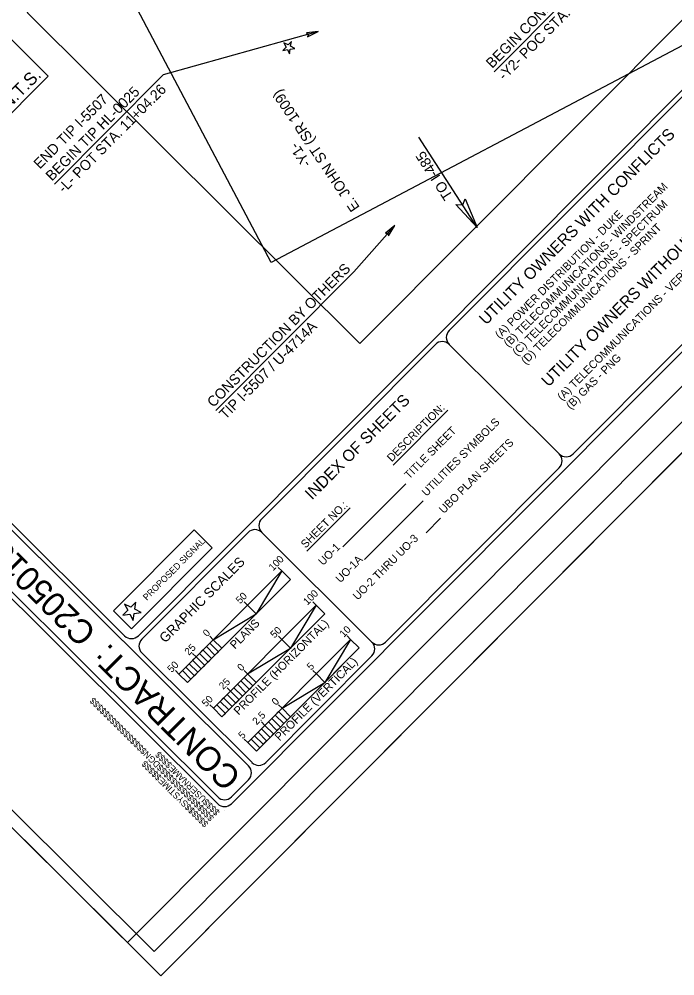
# Model space of a CAD drawing. Extents: x 1484850 to 1495577, y 495475 to 506245.
# Drawn here: x 1486921 to 1488945, y 495475 to 498431 of the extents above; entities that cross this region are included whole.
import ezdxf

# ---------------------------------------------------------------- set-up
doc = ezdxf.new("R2010")
doc.units = 0
for name, color, linetype in [('Cell Prop Down Guy _B', 7, 'Continuous'), ('Exist Conduit _B', 7, 'Continuous'), ('Exist Utilities Power UG Cable SUE LOS C', 7, 'Continuous'), ('Exist Utilities Sanitary Sewer Manhole CELL', 7, 'Continuous'), ('Exist Utilities Telephone Pedestal CELL', 7, 'Continuous'), ('Exist Utilities Telephone UG Cable SUE LOS C', 7, 'Continuous'), ('Exist Utilities Telephone UG FO SUE LOS C', 7, 'Continuous'), ('Exist Utilities TV UG Cable SUE LOS C', 7, 'Continuous'), ('Exist Utilities Water Meter CELL', 7, 'Continuous'), ('Exist Utilities Water UG Line SUE LOS B', 7, 'Continuous'), ('Exist Utilities Water Valve CELL', 7, 'Continuous'), ('P Pole (Pow Co) CELL', 7, 'Continuous'), ('Prop Guy Wire', 7, 'Continuous'), ('Prop UG Pow Cables', 7, 'Continuous')]:
    doc.layers.add(name, color=color, linetype=linetype)

msp = doc.modelspace()

# ---------------------------------------------------------------- linework, layer by layer
at = {"layer": 'Cell Prop Down Guy _B'}
for p, q in [((1487357.7, 495475.3), (1490922.5, 499055)), ((1485019.4, 497803.9), (1487357.7, 495475.3))]:
    msp.add_line(p, q, dxfattribs=at)
msp.add_lwpolyline([(1485019.4, 497803.9), (1488584.2, 501383.6), (1490922.5, 499055), (1487357.7, 495475.3)], close=True, dxfattribs=at)
at = {"layer": 'Exist Conduit _B'}
for p, q in [((1487731.5, 496726.7), (1487720.9, 496737.3)), ((1487625.7, 496620.5), (1487615.1, 496631)), ((1487466.9, 496461), (1487456.3, 496471.6)), ((1487414, 496407.9), (1487403.4, 496418.4)), ((1487555.1, 495985.8), (1487555.1, 495985.8))]:
    msp.add_line(p, q, dxfattribs=at)
at = {"layer": 'Exist Utilities Power UG Cable SUE LOS C'}
for p, q in [((1488075.3, 497053.3), (1488244.1, 497222.9)), ((1487920.3, 496801.3), (1488114.2, 496996)), ((1487987.3, 496761.4), (1488167.8, 496942.6)), ((1487809.4, 496787.4), (1487943, 496921.1)), ((1488177.1, 496844.7), (1488221.4, 496889.2))]:
    msp.add_line(p, q, dxfattribs=at)
at = {"layer": 'Exist Utilities Sanitary Sewer Manhole CELL'}
for points in [[(1487811.4, 498377.2), (1487844.4, 498392.9), (1487807.8, 498389.3), (1487813.9, 498384.4)], [(1488297.6, 497876.3), (1488335.3, 497788.1), (1488269.5, 497858.8), (1488290.2, 497857.8)], [(1488061.2, 497762.3), (1488080.4, 497793.4), (1488051.6, 497770.5), (1488059.5, 497769.8)]]:
    msp.add_lwpolyline(points, close=True, dxfattribs=at)
at = {"layer": 'Exist Utilities Telephone Pedestal CELL'}
for points in [[(1487744.7, 498345.3), (1487734.4, 498335), (1487748.8, 498337.3), (1487755.4, 498324.4), (1487757.6, 498338.7), (1487772, 498341), (1487759, 498347.6), (1487761.3, 498361.9), (1487751, 498351.6), (1487738, 498358.2), (1487744.7, 498345.3)], [(1487256.1, 496604.9), (1487240.7, 496589.5), (1487262.2, 496592.9), (1487272.2, 496573.5), (1487275.5, 496595.1), (1487297, 496598.5), (1487277.6, 496608.4), (1487281, 496629.9), (1487265.6, 496614.4), (1487246.1, 496624.3), (1487256.1, 496604.9)]]:
    msp.add_lwpolyline(points, dxfattribs=at)
at = {"layer": 'Exist Utilities Telephone UG Cable SUE LOS C'}
msp.add_lwpolyline([(1486945.7, 498451.8), (1488980.9, 500495.4), (1490008.1, 499472.4), (1487973, 497428.8)], close=True, dxfattribs=at)
msp.add_lwpolyline([(1486945.7, 498451.8), (1488980.9, 500495.4), (1490008.1, 499472.4), (1487973, 497428.8)], close=True, dxfattribs=at)
at = {"layer": 'Exist Utilities Telephone UG FO SUE LOS C'}
msp.add_lwpolyline([(1487208.7, 498608.1), (1488222.1, 499143.2), (1488965.4, 498493.7), (1489025.4, 498380), (1487698.9, 497679.6)], close=True, dxfattribs=at)
at = {"layer": 'Exist Utilities TV UG Cable SUE LOS C'}
msp.add_lwpolyline([(1487211.7, 496602.9), (1487460.9, 496853.2), (1487516.6, 496797.6), (1487267.4, 496547.4)], close=True, dxfattribs=at)
at = {"layer": 'Exist Utilities Water Meter CELL'}
msp.add_line((1488335.3, 497788.1), (1488154.6, 498067.2), dxfattribs=at)
msp.add_lwpolyline([(1486217.1, 497689.6), (1486895.2, 498370.5), (1487010.5, 498255.7), (1486332.4, 497574.8)], close=True, dxfattribs=at)
at = {"layer": 'Exist Utilities Water UG Line SUE LOS B'}
for p, q in [((1488751.5, 498634.5), (1488387.4, 498268.8)), ((1487844.4, 498392.9), (1487365, 498259)), ((1487365, 498259), (1487029.3, 497921.9)), ((1487954.1, 497650.7), (1488080.4, 497793.4)), ((1487954.1, 497650.7), (1487527.6, 497222.4))]:
    msp.add_line(p, q, dxfattribs=at)
at = {"layer": 'P Pole (Pow Co) CELL'}
msp.add_lwpolyline([(1488481.3, 501486.1), (1484916.4, 497906.4), (1487254.7, 495577.9), (1490819.6, 499157.6)], close=True, dxfattribs=at)
at = {"layer": 'Prop Guy Wire'}
msp.add_lwpolyline([(1487337.5, 495550.5), (1490865.3, 499093), (1488622.4, 501326.5), (1485094.6, 497784)], close=True, dxfattribs=at)
at = {"layer": 'Prop UG Pow Cables'}
for p, q in [((1487288.8, 496526.2), (1490294.8, 499544.7)), ((1488248.5, 497469), (1489172, 498396.3)), ((1487246.4, 496526.1), (1485471.4, 498293.7)), ((1487629, 496123.8), (1485460.8, 498283.1)), ((1487669.7, 496887.8), (1488206.1, 497426.6)), ((1488248.6, 497426.5), (1488588.7, 497087.8)), ((1487299.4, 496515.5), (1487627.5, 496845.1)), ((1487670, 496845.1), (1488010.1, 496506.4)), ((1487731.5, 496726.7), (1487414, 496407.8)), ((1487731.5, 496726.7), (1487720.9, 496737.3)), ((1487758.1, 496700.2), (1487731.5, 496726.7)), ((1487440.5, 496381.4), (1487758.1, 496700.2)), ((1487837.8, 496620.8), (1487827.2, 496631.5)), ((1487837.8, 496620.8), (1487827.2, 496631.5)), ((1487837.8, 496620.8), (1487520.3, 496302)), ((1487837.8, 496620.8), (1487520.3, 496302)), ((1487625.7, 496620.4), (1487615.1, 496631)), ((1487625.7, 496620.4), (1487652.2, 496593.9)), ((1487864.4, 496594.4), (1487837.8, 496620.8)), ((1487546.8, 496275.5), (1487864.4, 496594.4)), ((1487519.8, 496514.1), (1487509.2, 496524.7)), ((1487944.1, 496515), (1487626.6, 496196.1)), ((1487944.1, 496515), (1487626.6, 496196.1)), ((1487944.1, 496515), (1487626.6, 496196.1)), ((1487732, 496514.6), (1487721.3, 496525.1)), ((1487732, 496514.6), (1487721.3, 496525.1)), ((1487732, 496514.6), (1487758.5, 496488.1)), ((1487944.1, 496515), (1487933.5, 496525.6)), ((1487944.1, 496515), (1487933.5, 496525.6)), ((1487944.1, 496515), (1487933.5, 496525.6)), ((1487970.7, 496488.5), (1487944.1, 496515)), ((1487653.1, 496169.7), (1487970.7, 496488.5)), ((1487639.7, 496134.4), (1487299.5, 496473.1)), ((1487466.9, 496461), (1487456.3, 496471.6)), ((1487488.1, 496482.2), (1487514.6, 496455.8)), ((1487414, 496407.8), (1487403.4, 496418.4)), ((1487403.4, 496418.4), (1487403.4, 496418.4)), ((1487414, 496407.8), (1487440.5, 496381.4)), ((1487414, 496407.8), (1487414, 496407.8)), ((1487626.1, 496408.3), (1487615.5, 496418.8)), ((1487626.1, 496408.3), (1487615.5, 496418.8)), ((1487838.3, 496408.7), (1487827.6, 496419.3)), ((1487838.3, 496408.7), (1487827.6, 496419.3)), ((1487838.3, 496408.7), (1487827.6, 496419.3)), ((1487838.3, 496408.7), (1487864.8, 496382.2)), ((1487573.2, 496355.1), (1487562.6, 496365.7)), ((1487573.2, 496355.1), (1487562.6, 496365.7)), ((1487594.4, 496376.4), (1487620.9, 496349.9)), ((1487520.3, 496302), (1487509.6, 496312.6)), ((1487520.3, 496302), (1487509.6, 496312.6)), ((1487509.6, 496312.6), (1487509.6, 496312.6)), ((1487732.4, 496302.4), (1487721.8, 496313)), ((1487732.4, 496302.4), (1487721.8, 496313)), ((1487732.4, 496302.4), (1487721.8, 496313)), ((1487520.3, 496302), (1487546.8, 496275.5)), ((1487520.3, 496302), (1487520.3, 496302)), ((1487520.3, 496302), (1487520.3, 496302)), ((1487679.5, 496249.3), (1487668.9, 496259.8)), ((1487679.5, 496249.3), (1487668.9, 496259.8)), ((1487679.5, 496249.3), (1487668.9, 496259.8)), ((1487700.7, 496270.5), (1487727.2, 496244.1)), ((1487626.6, 496196.1), (1487615.9, 496206.7)), ((1487626.6, 496196.1), (1487615.9, 496206.7)), ((1487626.6, 496196.1), (1487615.9, 496206.7)), ((1487615.9, 496206.7), (1487615.9, 496206.7)), ((1487626.6, 496196.1), (1487653.1, 496169.7)), ((1487626.6, 496196.1), (1487626.6, 496196.1)), ((1487626.6, 496196.1), (1487626.6, 496196.1)), ((1487626.6, 496196.1), (1487626.6, 496196.1)), ((1487555.1, 495985.8), (1487555.1, 495985.8)), ((1487555.1, 495985.8), (1487555.1, 495985.8)), ((1487555.1, 495985.8), (1487555.1, 495985.8)), ((1487555.1, 495985.8), (1487555.1, 495985.8))]:
    msp.add_line(p, q, dxfattribs=at)
for points in [[(1487576.3, 496007), (1490709.3, 499153.1)], [(1485344.3, 498187.4), (1487533.8, 496006.9)], [(1485344.3, 498187.4), (1487533.8, 496006.9)], [(1485365.6, 498187.4), (1487533.8, 496028.2)], [(1488631.1, 497087.9), (1489554.7, 498015.2)], [(1488052.3, 496506.7), (1488588.7, 497045.5)], [(1487682.1, 496134.5), (1488010.2, 496464)], [(1487576.2, 496028.2), (1487629.1, 496081.4)]]:
    msp.add_lwpolyline(points, dxfattribs=at)
for points in [[(1486217.1, 497689.6), (1486895.2, 498370.5), (1487010.5, 498255.7), (1486332.4, 497574.8)], [(1487731.5, 496726.7), (1487652.2, 496593.9), (1487758.1, 496700.2)], [(1487837.8, 496620.8), (1487758.5, 496488.1), (1487864.4, 496594.4)], [(1487519.8, 496514.1), (1487652.2, 496593.9), (1487546.4, 496487.6)], [(1487944.1, 496515), (1487864.8, 496382.2), (1487970.7, 496488.5)], [(1487498.7, 496492.9), (1487509.2, 496503.5), (1487535.8, 496477), (1487525.2, 496466.4)], [(1487626.1, 496408.3), (1487758.5, 496488.1), (1487652.7, 496381.8)], [(1487456.3, 496450.3), (1487466.9, 496461), (1487493.5, 496434.5), (1487482.9, 496423.9)], [(1487477.5, 496471.6), (1487488.1, 496482.2), (1487514.6, 496455.8), (1487504.1, 496445.1)], [(1487435.1, 496429.1), (1487445.8, 496439.7), (1487472.3, 496413.2), (1487461.8, 496402.6)], [(1487414, 496407.8), (1487424.6, 496418.5), (1487451.1, 496392), (1487440.5, 496381.4)], [(1487604.9, 496387), (1487615.5, 496397.6), (1487642.1, 496371.2), (1487631.5, 496360.6)], [(1487583.8, 496365.7), (1487594.4, 496376.4), (1487620.9, 496349.9), (1487610.3, 496339.3)], [(1487732.4, 496302.4), (1487864.8, 496382.2), (1487759, 496276)], [(1487562.6, 496344.5), (1487573.2, 496355.1), (1487599.8, 496328.7), (1487589.2, 496318)], [(1487520.3, 496302), (1487530.8, 496312.6), (1487557.4, 496286.2), (1487546.8, 496275.5)], [(1487541.4, 496323.2), (1487552, 496333.9), (1487578.6, 496307.4), (1487568, 496296.8)], [(1487711.2, 496281.1), (1487721.8, 496291.8), (1487748.4, 496265.3), (1487737.8, 496254.7)], [(1487668.9, 496238.7), (1487679.5, 496249.3), (1487706.1, 496222.8), (1487695.5, 496212.2)], [(1487690.1, 496259.9), (1487700.7, 496270.5), (1487727.2, 496244.1), (1487716.6, 496233.5)], [(1487647.7, 496217.4), (1487658.3, 496228), (1487684.9, 496201.6), (1487674.3, 496190.9)], [(1487626.6, 496196.1), (1487637.2, 496206.7), (1487663.7, 496180.3), (1487653.1, 496169.7)]]:
    msp.add_lwpolyline(points, close=True, dxfattribs=at)
for centre, start, end in [((1488269.7, 497447.9), 135.1191, 225.1191), ((1488227.3, 497405.4), 45.1191, 135.1191), ((1488567.4, 497066.7), 315.1191, 45.1191), ((1488609.8, 497109.2), 225.1191, 315.1191), ((1487690.9, 496866.7), 135.1191, 225.1191), ((1487648.7, 496824), 45.1191, 135.1191), ((1487267.4, 496547.4), 225.1191, 315.1191), ((1487320.6, 496494.5), 135.1191, 225.1191), ((1488031, 496528), 225.1191, 315.1191), ((1487988.8, 496485.3), 315.1191, 45.1191), ((1487660.7, 496155.8), 225.1191, 315.1191), ((1487607.8, 496102.7), 315.1191, 45.1191), ((1487554.9, 496049.5), 225.1191, 315.1191), ((1487554.9, 496028.3), 225.1191, 315.1191)]:
    msp.add_arc(centre, 30, start, end, dxfattribs=at)

# ---------------------------------------------------------------- texts
at = {"layer": 'Exist Conduit _B'}
for s, p in [('100', (1487704.5, 496725.1)), ('100', (1487810.8, 496619.3)), ('50', (1487603, 496623.2)), ('50', (1487709.3, 496517.3)), ('10', (1487923.3, 496519.7)), ('25', (1487444.6, 496464.1)), ('50', (1487391.3, 496410.6)), ('5', (1487822.1, 496418.1)), ('25', (1487550.8, 496358.3)), ('50', (1487497.6, 496304.8)), ('2.5', (1487654, 496249.3)), ('5', (1487610.5, 496205.6))]:
    msp.add_text(s, height=22.5, rotation=45.1191, dxfattribs=at).set_placement(p)
at = {"layer": 'Exist Utilities Power UG Cable SUE LOS C'}
for s, height, p in [('UTILITY OWNERS WITH CONFLICTS', 35.926, (1488362.6, 497484.5)), ('UTILITY OWNERS WITHOUT CONFLICTS', 35.926, (1488555, 497293)), ('(B) TELECOMMUNICATIONS - WINDSTREAM', 24.717, (1488431.5, 497415.9)), ('(C) TELECOMMUNICATIONS - SPECTRUM', 24.717, (1488458.3, 497389.2)), ('(A) POWER DISTRIBUTION - DUKE', 24.717, (1488404.7, 497442.6)), ('(D) TELECOMMUNICATIONS - SPRINT', 24.717, (1488485.2, 497362.5)), ('(A) TELECOMMUNICATIONS - VERIZON', 24.717, (1488597.1, 497251.1)), ('(B) GAS - PNG', 24.717, (1488623.9, 497224.3)), ('INDEX OF SHEETS', 35.937, (1487824.8, 496944.3)), ('DESCRIPTION:', 24.724, (1488071.1, 497062.1)), ('UTILITIES SYMBOLS', 24.724, (1488178.4, 496955.3)), ('TITLE SHEET', 24.724, (1488124.8, 497008.7)), ('UBO PLAN SHEETS', 24.724, (1488232, 496901.9)), ('SHEET NO.:', 24.72, (1487805.1, 496795)), ('UO-2 THRU UO-3', 24.724, (1487965.9, 496634.7)), ('UO-1', 24.72, (1487858.7, 496741.5)), ('UO-1A', 24.72, (1487912.3, 496688.1))]:
    msp.add_text(s, height=height, rotation=45.1049, dxfattribs=at).set_placement(p)
at = {"layer": 'Exist Utilities Water Meter CELL'}
for s, height, rotation, p in [('BEGIN CONSTRUCTION', 32, 45.1191, (1488381.4, 498277.5)), ('-Y2- POC STA. 10+16.28', 32, 45.1191, (1488418.8, 498240.3)), ('N.T.S.', 39.2, 45.1191, (1486886.8, 498150.5)), ('-L- POT STA. 11+04.26', 32, 45.1191, (1487059.3, 497892)), ('END TIP I-5507', 32, 45.1191, (1486984.5, 497966.5)), ('BEGIN TIP HL-0025', 32, 45.1191, (1487021.9, 497929.2)), ('TO I-485', 32, 122.9223, (1488261.4, 497885.1)), ('CONSTRUCTION BY OTHERS', 32, 45.1191, (1487520.2, 497229.8)), ('TIP I-5507 / U-4714A', 32, 45.1191, (1487557.7, 497192.5)), ('PROPOSED SIGNAL', 20, 45.1186, (1487314.9, 496633.7))]:
    msp.add_text(s, height=height, rotation=rotation, dxfattribs=at).set_placement(p)
at = {"layer": 'Exist Utilities Water Valve CELL'}
for s, p in [('E. JOHN ST (SR 1009)', (1487973.4, 497849.9)), ('-Y1-', (1487824, 497986.4))]:
    msp.add_text(s, height=32, rotation=123.8699, dxfattribs=at).set_placement(p)
at = {"layer": 'Prop UG Pow Cables'}
for s, height, rotation, p in [('C205013', 75, 135.1191, (1487162.7, 496540)), ('GRAPHIC SCALES', 29.999, 45.1191, (1487371.6, 496502.2)), ('PLANS', 25.5, 45.1191, (1487586.7, 496483.5)), ('PROFILE (HORIZONTAL)', 25.499, 45.1191, (1487598.2, 496279.6)), ('0', 22.5, 45.1191, (1487501, 496521.3)), ('CONTRACT:', 75, 135.1191, (1487610.3, 496094.2)), ('PROFILE (VERTICAL)', 25.499, 45.1191, (1487724.9, 496199.6)), ('0', 22.5, 45.1191, (1487607.2, 496415.4)), ('0', 22.5, 45.1191, (1487607.5, 496415.1)), ('$$$$$$$$$$$$$$$$DGN$$$$$$$$$$$$$$$$', 19.687, 135.1191, (1487523.9, 495965.1)), ('0', 22.5, 45.1191, (1487713.5, 496309.6)), ('0', 22.5, 45.1191, (1487713.8, 496309.3)), ('0', 22.5, 45.1191, (1487713.8, 496309.3)), ('$$$$USERNAME$$$$', 19.687, 135.1191, (1487541.6, 495982.2)), ('$$$$$$SYSTIME$$$$$', 19.687, 135.1191, (1487506.4, 495946.5))]:
    msp.add_text(s, height=height, rotation=rotation, dxfattribs=at).set_placement(p)

doc.saveas('drawing.dxf')
